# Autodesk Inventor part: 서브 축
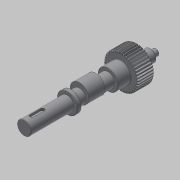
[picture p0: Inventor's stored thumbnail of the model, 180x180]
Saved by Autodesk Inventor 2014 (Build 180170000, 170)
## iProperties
Created: 2016-02
Part Number: 서브 축
Material: 일반
Document SubType Name: Modeling
Designer: mdu
Categories: <?xml version="1.0" encoding="UTF-16"?> <MemberInstance><Categories><FamilyTemplate><FamilyTemplateParameter ValueType="xs:double" Id="1" ObjectReferenceKey="da
Density: 1 g/cm^3
Mass: 506.173 g
Surface Area: 164.116 cm^2
Volume: 64.3986 cm^3
Appearance: 기본값
CustomPartVersion: 1
Author: mdu
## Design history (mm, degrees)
sketch "Sketch1"
  geometry: C1 r 21 at (0, 0)
  constraints: 1 centre point
  dimensions: "d0" = 42 diameter of C1 (= da_da)
extrude "Extrusion1" new body sketch "Sketch1" distance "d1" = 20 (= da_b); taper "d2" = 0 deg
workplane "Work Plane2"
feature "피치 지름" dims "d4" = 10, "d5" = 0
workplane "Work Plane8"
workplane "Work Plane9"
chamfer "모따기1" distance "d49" = 1; stored, may be unused: second distance "d50" = 2, angle "d51" = 45 deg
sketch "스케치3"
  geometry: C1 r 12.5 at (0, 0); 1 further point
  constraints: 1 centre point, 1 coincident
  dimensions: "d52" = 25 diameter of C1
extrude "돌출2" join sketch "스케치3" distance "d53" = 16; taper "d54" = 0 deg
sketch "스케치4"
  geometry: C1 r 8.5 at (0, 0); 1 further point
  constraints: 1 centre point, 1 coincident
  dimensions: "d55" = 17 diameter of C1
extrude "돌출3" join sketch "스케치4" distance "d56" = 103; taper "d57" = 0 deg
sketch "스케치5"
  geometry: C1 r 7.5 at (0, 0); 1 further point
  constraints: 1 centre point, 1 coincident
  dimensions: "d62" = 15 diameter of C1
extrude "돌출4" join sketch "스케치5" distance "d63" = 16; taper "d64" = 0 deg
sketch "스케치6"
  geometry: C1 r 4 at (0, 0); 1 further point
  constraints: 1 centre point, 1 coincident
  dimensions: "d65" = 8 diameter of C1
extrude "돌출5" join sketch "스케치6" distance "d66" = 7; taper "d67" = 0 deg
chamfer "모따기2" distance "d58" = 0.5; stored, may be unused: second distance "d59" = 2, angle "d60" = 45 deg
fillet "모깎기1" dims "d61" = 0.5
feature "스퍼 기어" dims "da_b" = 20, "da_d" = 40, "da_aw" = 31, "da_da" = 42, "da_df" = 37.5, "da_dw" = 40, angle "da_beta" = 0 deg, "da_lefttooth" = 0, "da_righttooth" = 0
node "작업 평면11"
sketch "스케치7"
  geometry: C1 r 8.5 at (0, 0) reference; C2 r 11.5 at (0, 3); 1 further point
  constraints: 1 centre point, 1 tangent, 1 vertical alignment
  dimensions: "d71" = 3 distance of C2.centre point (0, 0); "d72" = 23 diameter of C2 (derived)
extrude "돌출6" join sketch "스케치7" stored distance "d73" = 20; taper "d74" = 0 deg
node "작업 평면12"
sketch "스케치8"
  geometry: C1 r 12.5 at (0, 0) reference; 1 further point
extrude "돌출7" join sketch "스케치8" distance "d76" = 5; taper "d77" = 0 deg
chamfer "모따기3" distance "d78" = 0.5; stored, may be unused: second distance "d79" = 2, angle "d80" = 45 deg
sketch "스케치9"
  geometry: L1 (-8.5, 86)-(-8.5, 138.5) reference; L2 (-8, 139)-(8, 139) reference; L3 (0, 0)-(0, 139); L4 (-8.5, 115)-(0, 115); L5 (-8.5, 115)-(-8.5, 113.5); L6 (-7, 115)-(-8.5, 113.5)
  constraints: 8 end point, 4 point on line, 1 midpoint, 1 perpendicular
  dimensions: "d81" = 24 distance between parallel lines of L2 L4; "d82" = 45 deg angle of L6 L5; "d83" = 3 diameter of L5.end L4
revolve "회전1" sketch "스케치9" stored, may be unused: angle "d84" = 90 deg
sketch "스케치10"
  geometry: L1 (-8.5, 113.5)-(-7, 115) reference; L2 (-8.5, 116.5)-(-7, 115) reference; 2 further points
  constraints: 1 coincident
node "작업점1"
node "작업 평면14"
sketch "스케치11"
  geometry: L1 (8.5, 102.5)-(-8.5, 102.5) reference; L2 (0, 102.5)-(0, -36); L3 (-2.5, 93.5)-(-2.5, 80.5); L4 (2.5, 80.5)-(2.5, 93.5); L5 (-8, 103)-(8, 103) reference; A1 r 2.5 centre (0, 93.5) between (2.5, 93.5) and (-2.5, 93.5); A2 r 2.5 centre (0, 80.5) between (-2.5, 80.5) and (2.5, 80.5)
  constraints: 6 end point, 4 point on circle, 4 tangent, 2 centre point, 1 midpoint, 1 parallel, 1 perpendicular, 1 point on line, 1 vertical alignment
  dimensions: "d85" = 7 distance edge to line of A1 L5; "d86" = 18 dimension on A2 A1; "d87" = 5 distance between parallel lines of L3 L4
extrude "돌출8" cut sketch "스케치11" distance "d88" = 3; taper "d89" = 0 deg
body "Solid1"
sketch "Sketch2"
  geometry: C1 r 21 at (0, 0) reference; C2 r 20 at (0, 0)
  constraints: 1 centre point, 1 coincident
  dimensions: "d3" = 40 diameter of C2 (= da_dw)
body "Srf1"
other parameters: "d16" = 31 (= da_aw), "d17" = 0, "d34" = 4.5 deg (computed from da_z), "d39" = 0, "d41" = 0, "d43" = 31 (= da_aw), "d46" = 31 (= da_aw), "d47" = 0, "d48" = 0, "d68" = 25
